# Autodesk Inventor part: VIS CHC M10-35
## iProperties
Created: 2004-11
Part Number: VIS CHC M10-35
Document SubType Name: Modeling
Designer: Bruno
Manufacturer: Standard
Standards Organization: Custom
Author: Bruno
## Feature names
1. Base1
